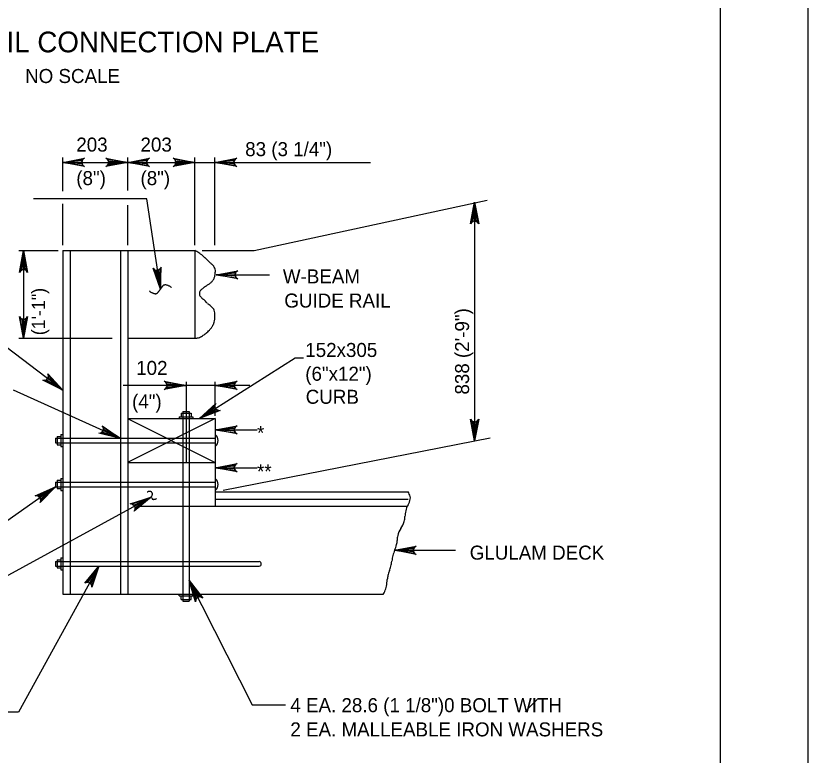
# Model space of a CAD drawing. Extents: x 0 to 36.3, y -66 to 0.
# Drawn here: x 27.22 to 34, y -12.54 to -6.22 of the extents above; entities that cross this region are included whole.
import ezdxf

# ---------------------------------------------------------------- set-up
doc = ezdxf.new("R2010")
doc.units = 0
for name, color, linetype in [('1', 7, 'Continuous'), ('2', 7, 'Continuous'), ('3', 7, 'Continuous'), ('63', 7, 'Continuous')]:
    doc.layers.add(name, color=color, linetype=linetype)

msp = doc.modelspace()

# ---------------------------------------------------------------- linework, layer by layer
at = {"layer": '1'}
msp.add_lwpolyline([(1.75, -21.25), (33.25, -21.25), (33.25, -0.75), (1.75, -0.75)], close=True, dxfattribs=at)
at = {"layer": '2'}
for p, q in [((27.6262, -8.2257), (27.6262, -11.1632)), ((27.6262, -8.2257), (28.7561, -8.2257)), ((27.6887, -8.2257), (27.6887, -11.1632)), ((28.1197, -8.2257), (28.1197, -11.1632)), ((28.1822, -8.2257), (28.1822, -11.1632)), ((28.7561, -8.2257), (28.7561, -8.9757)), ((28.1822, -8.9757), (28.7561, -8.9757)), ((28.6375, -9.6163), (28.7235, -9.6163)), ((28.6375, -9.6163), (28.6375, -9.6476)), ((28.6532, -9.6007), (28.7078, -9.6007)), ((28.6532, -9.6007), (28.6532, -11.2257)), ((28.7078, -9.6007), (28.7078, -11.2257)), ((28.7235, -9.6163), (28.7235, -9.6476)), ((28.1807, -9.6632), (28.9307, -9.6632)), ((28.9307, -9.6632), (28.1807, -10.0382)), ((28.1807, -9.6632), (28.9307, -10.0382)), ((28.6219, -9.6476), (28.6219, -9.6632)), ((28.6219, -9.6476), (28.7391, -9.6476)), ((28.7391, -9.6476), (28.7391, -9.6632)), ((28.9307, -9.6632), (28.9307, -10.0382)), ((27.5791, -9.8156), (27.5791, -9.8859)), ((27.5791, -9.8156), (27.6103, -9.8156)), ((27.6103, -9.7999), (27.626, -9.7999)), ((27.6103, -9.7999), (27.6103, -9.9015)), ((27.5635, -9.8312), (27.5635, -9.8703)), ((27.5635, -9.8312), (28.9307, -9.8312)), ((27.5635, -9.8703), (28.9307, -9.8703)), ((27.5791, -9.8859), (27.6103, -9.8859)), ((27.6103, -9.9015), (27.626, -9.9015)), ((28.1807, -10.0382), (28.9307, -10.0382)), ((28.9307, -10.0382), (28.9307, -10.4132)), ((27.5635, -10.2062), (27.5635, -10.2453)), ((27.5635, -10.2062), (28.9307, -10.2062)), ((27.5791, -10.1906), (27.5791, -10.2609)), ((27.5791, -10.1906), (27.6103, -10.1906)), ((27.6103, -10.1749), (27.6103, -10.2765)), ((27.6103, -10.1749), (27.626, -10.1749)), ((27.5635, -10.2453), (28.9307, -10.2453)), ((27.5791, -10.2609), (27.6103, -10.2609)), ((27.6103, -10.2765), (27.626, -10.2765)), ((28.9307, -10.2882), (30.5787, -10.2882)), ((28.9307, -10.3507), (30.5787, -10.3507)), ((28.2752, -10.4132), (30.5718, -10.4132)), ((27.5635, -10.8861), (27.5635, -10.9251)), ((27.5635, -10.8861), (29.3065, -10.8861)), ((27.5791, -10.8704), (27.6103, -10.8704)), ((27.5791, -10.8704), (27.5791, -10.9407)), ((27.6103, -10.8548), (27.626, -10.8548)), ((27.6103, -10.8548), (27.6103, -10.9563)), ((27.5635, -10.9251), (29.3065, -10.9251)), ((27.5791, -10.9407), (27.6103, -10.9407)), ((27.6103, -10.9563), (27.626, -10.9563)), ((27.6262, -11.1632), (30.3696, -11.1632)), ((28.6219, -11.1788), (28.6219, -11.1632)), ((28.7391, -11.1788), (28.7391, -11.1632)), ((28.6219, -11.1788), (28.7391, -11.1788)), ((28.6375, -11.2101), (28.6375, -11.1788)), ((28.6375, -11.2101), (28.7235, -11.2101)), ((28.6532, -11.2257), (28.7078, -11.2257)), ((28.7235, -11.2101), (28.7235, -11.1788))]:
    msp.add_line(p, q, dxfattribs=at)
for centre, radius, start, end in [((28.5619, -8.6186), 0.4382, 58.80055, 63.70691), ((28.7232, -8.3524), 0.127, 49.6783, 58.80055), ((24.7768, -13.0022), 6.2256, 49.24184, 49.6783), ((28.7474, -8.3954), 0.1439, 46.37044, 49.24184), ((15.7483, -22.0317), 18.9834, 46.30642, 46.37045), ((43.1981, 6.6993), 20.7527, 226.30642, 226.36766), ((32.4297, -4.5958), 5.1471, 226.36766, 226.55112), ((22.0681, -15.5342), 9.9198, 46.41897, 46.55112), ((28.8517, -8.406), 0.0797, 34.99719, 46.41896), ((28.8221, -8.4268), 0.1158, 25.52935, 34.99719), ((28.8872, -8.3957), 0.0437, 1.46908, 25.52935), ((28.7402, -8.3994), 0.1908, 350.02269, 1.46908), ((28.8754, -8.446), 0.0482, 328.7272, 343.49264), ((28.6865, -8.39), 0.2453, 343.49264, 350.02269), ((29.9598, -10.073), 1.9003, 125.19069, 126.12128), ((28.1249, -7.471), 1.2836, 305.19069, 306.32294), ((28.8139, -8.4082), 0.1204, 306.32294, 317.48407), ((28.8152, -8.4094), 0.1187, 317.48407, 328.72721), ((28.8481, -8.5951), 0.0529, 165.97254, 185.44137), ((28.8225, -8.5975), 0.0272, 185.44137, 212.72014), ((28.8724, -8.6012), 0.078, 155.22067, 165.97254), ((28.8137, -8.5741), 0.0133, 129.00416, 155.22067), ((28.9914, -8.7935), 0.2956, 126.86461, 129.00416), ((30.2831, -10.5161), 2.4488, 126.12128, 126.86461), ((28.8781, -8.5618), 0.0933, 212.72014, 220.60673), ((28.8861, -8.555), 0.1038, 220.60674, 228.08526), ((28.9364, -8.4989), 0.1792, 228.08526, 233.91812), ((28.7757, -8.7195), 0.0938, 45.85179, 53.91812), ((28.7686, -8.7268), 0.104, 36.09623, 45.85179), ((28.9104, -8.6234), 0.0716, 216.09623, 227.85892), ((28.968, -8.5598), 0.1573, 227.85893, 232.11616), ((28.5958, -9.0381), 0.4487, 49.59564, 52.11616), ((28.6461, -8.979), 0.3711, 46.64207, 49.59564), ((28.7178, -8.9031), 0.2667, 43.15795, 46.64207), ((28.8827, -8.7485), 0.0406, 20.32672, 43.15795), ((28.8249, -8.7699), 0.1023, 5.99987, 20.32672), ((28.6716, -8.7765), 0.256, 352.04502, 358.45154), ((28.7431, -8.7785), 0.1845, 358.45154, 5.99988), ((28.7341, -8.7637), 0.2035, 323.00641, 329.73877), ((28.8326, -8.8212), 0.0895, 329.73877, 339.90105), ((28.8227, -8.8176), 0.1, 339.90105, 347.90299), ((28.5559, -8.7604), 0.3728, 347.90299, 352.04503), ((28.7328, -8.7939), 0.1826, 304.07209, 310.93928), ((28.569, -8.6051), 0.4325, 310.93928, 315.90388), ((28.7278, -8.7589), 0.2114, 315.90388, 323.00641), ((28.7446, -8.7871), 0.189, 273.48514, 283.05905), ((28.7735, -8.912), 0.0607, 283.05905, 299.98923), ((28.546, -8.5177), 0.5161, 299.98923, 304.07209), ((28.8882, -9.8507), 0.0661, 309.84987, 50.15014), ((28.8882, -10.2257), 0.0661, 309.84987, 50.15014), ((30.427, -10.38), 0.1772, 16.85937, 31.17642), ((30.4466, -10.3213), 0.154, 329.0266, 348.78562), ((30.5518, -10.3421), 0.0468, 348.78562, 16.85937), ((30.7196, -10.4851), 0.1643, 149.0266, 168.1522), ((30.9017, -10.5233), 0.3504, 168.15221, 176.42716), ((30.3778, -10.5012), 0.1729, 323.40858, 346.27514), ((30.3195, -10.487), 0.233, 346.27514, 356.42716), ((30.6385, -10.6947), 0.1517, 143.40858, 167.83875), ((30.6931, -10.7065), 0.2076, 167.83875, 179.70998), ((30.1526, -10.6548), 0.3393, 336.60186, 345.34306), ((30.3435, -10.7047), 0.142, 345.34306, 359.70998), ((31.0199, -10.9716), 0.587, 166.38398, 171.19227), ((30.7128, -10.8972), 0.271, 156.60185, 166.38398), ((29.3038, -10.9056), 0.0197, 277.85987, 82.14013), ((29.949, -10.8056), 0.4967, 345.96444, 351.19227), ((30.8518, -11.1187), 0.4592, 160.48289, 165.77345), ((30.0158, -10.8223), 0.4278, 340.48289, 345.96444), ((29.7735, -10.9867), 0.6299, 349.9453, 355.29217), ((30.5997, -11.0547), 0.1991, 165.77345, 175.29217), ((30.2546, -11.072), 0.1413, 340.08642, 349.9453), ((29.8972, -10.9425), 0.5214, 334.95891, 340.08642)]:
    msp.add_arc(centre, radius, start, end, dxfattribs=at)
at = {"layer": '3'}
for p, q in [((27.6264, -7.7166), (27.6264, -7.4293)), ((28.1816, -7.7118), (28.1816, -7.4293)), ((28.7555, -8.1782), (28.7555, -7.4293)), ((28.9273, -8.1782), (28.9273, -7.4293)), ((27.6264, -7.4709), (30.2583, -7.4709)), ((27.6264, -8.1782), (27.6264, -7.8264)), ((28.1816, -8.1782), (28.1816, -7.836)), ((29.2632, -8.2257), (31.2546, -7.7952)), ((31.1481, -7.8115), (31.1481, -9.8539)), ((27.2502, -8.2257), (27.5856, -8.2257)), ((27.2908, -8.2257), (27.2908, -8.9757)), ((28.8175, -8.2257), (29.2632, -8.2257)), ((28.9377, -8.4325), (29.3937, -8.4325)), ((27.6262, -9.4195), (26.6547, -8.6821)), ((27.2502, -8.9757), (28.0497, -8.9757)), ((28.7952, -9.6632), (29.6144, -9.1422)), ((29.6144, -9.1422), (29.6861, -9.1422)), ((28.6807, -9.3471), (28.6807, -10.0382)), ((28.9307, -9.6393), (28.9307, -9.3471)), ((29.227, -9.3783), (28.1421, -9.3783)), ((28.1197, -9.8325), (27.2061, -9.4198)), ((28.9307, -9.7589), (29.2888, -9.7589)), ((28.9969, -10.2752), (31.2809, -9.8279)), ((28.9307, -10.0826), (29.2888, -10.0826)), ((27.5635, -10.2453), (27.1487, -10.5407)), ((28.3833, -10.3342), (26.6133, -11.2992)), ((30.4618, -10.7895), (30.9847, -10.7895)), ((27.9353, -10.9251), (27.2464, -12.1727)), ((28.7078, -11.0472), (29.2468, -12.1111)), ((29.2468, -12.1111), (29.5322, -12.1111)), ((31.5794, -12.1696), (31.6839, -12.0651)), ((27.2464, -12.1727), (25.8767, -12.1727))]:
    msp.add_line(p, q, dxfattribs=at)
for points in [[(27.6264, -7.4709), (27.8128, -7.436), (27.7985, -7.4459), (27.7911, -7.4584), (27.7889, -7.4709), (27.7911, -7.4834), (27.7985, -7.4959), (27.8128, -7.5058), (27.6264, -7.4709), (27.7985, -7.4959), (27.7911, -7.4834), (27.6264, -7.4709), (27.7889, -7.4709), (27.7911, -7.4584), (27.6264, -7.4709), (27.7985, -7.4459)], [(28.1816, -7.4709), (27.9952, -7.5058), (28.0095, -7.4959), (28.0169, -7.4834), (28.0191, -7.4709), (28.0169, -7.4584), (28.0095, -7.4459), (27.9952, -7.436), (28.1816, -7.4709), (28.0095, -7.4459), (28.0169, -7.4584), (28.1816, -7.4709), (28.0191, -7.4709), (28.0169, -7.4834), (28.1816, -7.4709), (28.0095, -7.4959)], [(28.1816, -7.4709), (28.368, -7.436), (28.3537, -7.4459), (28.3462, -7.4584), (28.3441, -7.4709), (28.3462, -7.4834), (28.3537, -7.4959), (28.368, -7.5058), (28.1816, -7.4709), (28.3537, -7.4959), (28.3462, -7.4834), (28.1816, -7.4709), (28.3441, -7.4709), (28.3462, -7.4584), (28.1816, -7.4709), (28.3537, -7.4459)], [(28.7555, -7.4709), (28.5691, -7.5058), (28.5834, -7.4959), (28.5908, -7.4834), (28.593, -7.4709), (28.5908, -7.4584), (28.5834, -7.4459), (28.5691, -7.436), (28.7555, -7.4709), (28.5834, -7.4459), (28.5908, -7.4584), (28.7555, -7.4709), (28.593, -7.4709), (28.5908, -7.4834), (28.7555, -7.4709), (28.5834, -7.4959)], [(28.9273, -7.4709), (29.1137, -7.436), (29.0994, -7.4459), (29.092, -7.4584), (29.0898, -7.4709), (29.092, -7.4834), (29.0994, -7.4959), (29.1137, -7.5058), (28.9273, -7.4709), (29.0994, -7.4959), (29.092, -7.4834), (28.9273, -7.4709), (29.0898, -7.4709), (29.092, -7.4584), (28.9273, -7.4709), (29.0994, -7.4459)], [(28.4608, -8.5558), (28.3457, -7.7833), (27.3767, -7.7833)], [(31.1481, -7.8115), (31.183, -7.9979), (31.1731, -7.9836), (31.1606, -7.9762), (31.1481, -7.974), (31.1356, -7.9762), (31.1231, -7.9836), (31.1132, -7.9979), (31.1481, -7.8115), (31.1231, -7.9836), (31.1356, -7.9762), (31.1481, -7.8115), (31.1481, -7.974), (31.1606, -7.9762), (31.1481, -7.8115), (31.1731, -7.9836)], [(27.2908, -8.2257), (27.3257, -8.4122), (27.3158, -8.3978), (27.3033, -8.3904), (27.2908, -8.3882), (27.2783, -8.3904), (27.2658, -8.3978), (27.2559, -8.4122), (27.2908, -8.2257), (27.2658, -8.3978), (27.2783, -8.3904), (27.2908, -8.2257), (27.2908, -8.3882), (27.3033, -8.3904), (27.2908, -8.2257), (27.3158, -8.3978)], [(28.4608, -8.5558), (28.3987, -8.3766), (28.4108, -8.3893), (28.4608, -8.5558), (28.4242, -8.3948), (28.4369, -8.3951), (28.4608, -8.5558), (28.4489, -8.3912), (28.4602, -8.382), (28.4608, -8.5558), (28.4679, -8.3663), (28.4602, -8.382), (28.4489, -8.3912), (28.4369, -8.3951), (28.4242, -8.3948), (28.4108, -8.3893)], [(28.9377, -8.4325), (29.1242, -8.3976), (29.1098, -8.4075), (29.1024, -8.42), (29.1002, -8.4325), (29.1024, -8.445), (29.1098, -8.4575), (29.1242, -8.4674), (28.9377, -8.4325), (29.1098, -8.4575), (29.1024, -8.445), (28.9377, -8.4325), (29.1002, -8.4325), (29.1024, -8.42), (28.9377, -8.4325), (29.1098, -8.4075)], [(27.2908, -8.9757), (27.2559, -8.7893), (27.2658, -8.8037), (27.2783, -8.8111), (27.2908, -8.8133), (27.3033, -8.8111), (27.3158, -8.8037), (27.3257, -8.7893), (27.2908, -8.9757), (27.3158, -8.8037), (27.3033, -8.8111), (27.2908, -8.9757), (27.2908, -8.8133), (27.2783, -8.8111), (27.2908, -8.9757), (27.2658, -8.8037)], [(27.6262, -9.4195), (27.4567, -9.3347), (27.4741, -9.3354), (27.4876, -9.3299), (27.4968, -9.3212), (27.5027, -9.31), (27.5043, -9.2956), (27.4989, -9.2789), (27.6262, -9.4195), (27.5043, -9.2956), (27.5027, -9.31), (27.6262, -9.4195), (27.4968, -9.3212), (27.4876, -9.3299), (27.6262, -9.4195), (27.4741, -9.3354)], [(28.6807, -9.3783), (28.4942, -9.4132), (28.5086, -9.4033), (28.516, -9.3908), (28.5182, -9.3783), (28.516, -9.3658), (28.5086, -9.3533), (28.4942, -9.3434), (28.6807, -9.3783), (28.5086, -9.3533), (28.516, -9.3658), (28.6807, -9.3783), (28.5182, -9.3783), (28.516, -9.3908), (28.6807, -9.3783), (28.5086, -9.4033)], [(28.9307, -9.3783), (29.1171, -9.3434), (29.1028, -9.3533), (29.0953, -9.3658), (29.0932, -9.3783), (29.0953, -9.3908), (29.1028, -9.4033), (29.1171, -9.4132), (28.9307, -9.3783), (29.1028, -9.4033), (29.0953, -9.3908), (28.9307, -9.3783), (29.0932, -9.3783), (29.0953, -9.3658), (28.9307, -9.3783), (29.1028, -9.3533)], [(28.7952, -9.6632), (28.9337, -9.5337), (28.9269, -9.5498), (28.9274, -9.5643), (28.9322, -9.576), (28.9408, -9.5854), (28.9537, -9.592), (28.9712, -9.5927), (28.7952, -9.6632), (28.9537, -9.592), (28.9408, -9.5854), (28.7952, -9.6632), (28.9322, -9.576), (28.9274, -9.5643), (28.7952, -9.6632), (28.9269, -9.5498)], [(31.1481, -9.8539), (31.1132, -9.6675), (31.1231, -9.6818), (31.1356, -9.6892), (31.1481, -9.6914), (31.1606, -9.6892), (31.1731, -9.6818), (31.183, -9.6675), (31.1481, -9.8539), (31.1731, -9.6818), (31.1606, -9.6892), (31.1481, -9.8539), (31.1481, -9.6914), (31.1356, -9.6892), (31.1481, -9.8539), (31.1231, -9.6818)], [(28.1197, -9.8325), (27.9354, -9.7876), (27.9526, -9.7845), (27.9645, -9.7761), (27.9716, -9.7656), (27.9748, -9.7533), (27.9732, -9.7389), (27.9642, -9.7239), (28.1197, -9.8325), (27.9732, -9.7389), (27.9748, -9.7533), (28.1197, -9.8325), (27.9716, -9.7656), (27.9645, -9.7761), (28.1197, -9.8325), (27.9526, -9.7845)], [(28.9307, -9.7589), (29.1171, -9.724), (29.1028, -9.7339), (29.0953, -9.7464), (29.0932, -9.7589), (29.0953, -9.7714), (29.1028, -9.7839), (29.1171, -9.7938), (28.9307, -9.7589), (29.1028, -9.7839), (29.0953, -9.7714), (28.9307, -9.7589), (29.0932, -9.7589), (29.0953, -9.7464), (28.9307, -9.7589), (29.1028, -9.7339)], [(28.9307, -10.0826), (29.1171, -10.0477), (29.1028, -10.0576), (29.0953, -10.0701), (29.0932, -10.0826), (29.0953, -10.0951), (29.1028, -10.1076), (29.1171, -10.1175), (28.9307, -10.0826), (29.1028, -10.1076), (29.0953, -10.0951), (28.9307, -10.0826), (29.0932, -10.0826), (29.0953, -10.0701), (28.9307, -10.0826), (29.1028, -10.0576)], [(27.5635, -10.2453), (27.432, -10.3819), (27.4379, -10.3654), (27.4367, -10.351), (27.4312, -10.3396), (27.4222, -10.3306), (27.4088, -10.3247), (27.3914, -10.3249), (27.5635, -10.2453), (27.4088, -10.3247), (27.4222, -10.3306), (27.5635, -10.2453), (27.4312, -10.3396), (27.4367, -10.351), (27.5635, -10.2453), (27.4379, -10.3654)], [(28.3833, -10.3342), (28.2363, -10.4542), (28.2442, -10.4386), (28.2447, -10.424), (28.2406, -10.412), (28.2327, -10.4021), (28.2203, -10.3947), (28.2028, -10.3928), (28.3833, -10.3342), (28.2203, -10.3947), (28.2327, -10.4021), (28.3833, -10.3342), (28.2406, -10.412), (28.2447, -10.424), (28.3833, -10.3342), (28.2442, -10.4386)], [(30.4618, -10.7895), (30.6482, -10.7546), (30.6339, -10.7645), (30.6265, -10.777), (30.6243, -10.7895), (30.6265, -10.802), (30.6339, -10.8145), (30.6482, -10.8244), (30.4618, -10.7895), (30.6339, -10.8145), (30.6265, -10.802), (30.4618, -10.7895), (30.6243, -10.7895), (30.6265, -10.777), (30.4618, -10.7895), (30.6339, -10.7645)], [(27.9353, -10.9251), (27.8758, -11.1052), (27.8741, -11.0877), (27.8667, -11.0753), (27.8567, -11.0673), (27.8448, -11.0632), (27.8302, -11.0636), (27.8147, -11.0714), (27.9353, -10.9251), (27.8302, -11.0636), (27.8448, -11.0632), (27.9353, -10.9251), (27.8567, -11.0673), (27.8667, -11.0753), (27.9353, -10.9251), (27.8741, -11.0877)], [(28.7078, -11.0472), (28.8232, -11.1977), (28.8079, -11.1893), (28.7934, -11.1884), (28.7812, -11.1922), (28.7711, -11.1997), (28.7632, -11.2119), (28.7609, -11.2293), (28.7078, -11.0472), (28.7632, -11.2119), (28.7711, -11.1997), (28.7078, -11.0472), (28.7812, -11.1922), (28.7934, -11.1884), (28.7078, -11.0472), (28.8079, -11.1893)]]:
    msp.add_lwpolyline(points, dxfattribs=at)
for centre, radius, start, end in [((28.3708, -10.3131), 0.0294, 123.68829, 137.53367), ((28.3629, -10.3013), 0.0152, 104.37653, 123.68829), ((28.3725, -10.3387), 0.0538, 96.70939, 104.37653), ((28.3685, -10.3044), 0.0193, 83.89329, 96.70939), ((28.3671, -10.3173), 0.0323, 71.56621, 83.89329), ((28.37, -10.3085), 0.023, 56.9563, 71.56621), ((28.3683, -10.3111), 0.0261, 48.36838, 56.95631), ((28.366, -10.3138), 0.0297, 40.30852, 48.36838), ((28.3706, -10.3098), 0.0236, 25.01838, 40.30852), ((28.3855, -10.3344), 0.00232, 156.36921, 171.86395), ((28.3838, -10.3342), 0.000615, 171.86395, 206.56659), ((28.6884, -10.1819), 0.3412, 206.56659, 208.01729), ((29.051, -10.6256), 0.7287, 155.49801, 156.36921), ((28.6364, -10.2096), 0.2822, 208.01729, 209.74654), ((28.8279, -10.5239), 0.4836, 154.82607, 155.49801), ((28.1812, -10.22), 0.231, 334.82607, 335.79824), ((28.4091, -10.3395), 0.0204, 209.74654, 216.18641), ((28.3777, -10.3083), 0.0156, 335.79824, 352.40485), ((28.3788, -10.306), 0.0146, 5.53818, 25.01837), ((28.3957, -10.3493), 0.00379, 216.18641, 259.38104), ((28.3685, -10.307), 0.0249, 352.40485, 5.53818), ((28.4013, -10.3195), 0.0341, 259.38104, 273.48518), ((28.3999, -10.2973), 0.0563, 273.48518, 278.97203), ((28.3917, -10.245), 0.1092, 278.97203, 282.91026), ((28.4105, -10.3274), 0.0248, 282.91026, 293.62796), ((28.397, -10.2965), 0.0584, 293.62796, 300.60031)]:
    msp.add_arc(centre, radius, start, end, dxfattribs=at)
msp.add_open_spline([(28.3645, -8.5702), (28.4198, -8.6111), (28.4608, -8.5558), (28.5018, -8.5005), (28.5571, -8.5415)], degree=2, dxfattribs=at)
at = {"layer": '63'}
msp.add_lwpolyline([(0, -22), (34, -22), (34, 0), (0, 0)], close=True, dxfattribs=at)

# ---------------------------------------------------------------- texts
at = {"layer": '2'}
msp.add_text('VIEW A @ 15.9 (5/8") GUIDE RAIL CONNECTION PLATE', height=0.177167, dxfattribs=at).set_placement((23.6348, -6.5297))
at = {"layer": '3'}
for s, p in [('NO SCALE', (27.3042, -6.7923)), ('203', (27.742, -7.3789)), ('203', (28.2909, -7.3789)), ('83 (3 1/4")', (29.1862, -7.418)), ('(8")', (27.742, -7.6656)), ('(8")', (28.2909, -7.6656)), ('W-BEAM', (29.5083, -8.5062)), ('GUIDE RAIL', (29.5206, -8.7133)), ('152x305', (29.6998, -9.1358)), ('102', (28.2538, -9.2895)), ('(6"x12")', (29.6998, -9.3392)), ('CURB', (29.7036, -9.5363)), ('(4")', (28.2189, -9.5762)), ('*', (29.2872, -9.8455)), ('**', (29.2872, -10.1749)), ('GLULAM DECK', (31.1061, -10.8693)), ('4 EA. 28.6 (1 1/8")0 BOLT WITH', (29.5723, -12.1742)), ('2 EA. MALLEABLE IRON WASHERS', (29.5723, -12.3813))]:
    msp.add_text(s, height=0.12, dxfattribs=at).set_placement(p)
for s, height, p in [('(1\'-1")', 0.114, (27.4757, -8.9497)), ('838 (2\'-9")', 0.12, (31.1005, -9.4572))]:
    msp.add_text(s, height=height, rotation=90, dxfattribs=at).set_placement(p)

doc.saveas('drawing.dxf')
